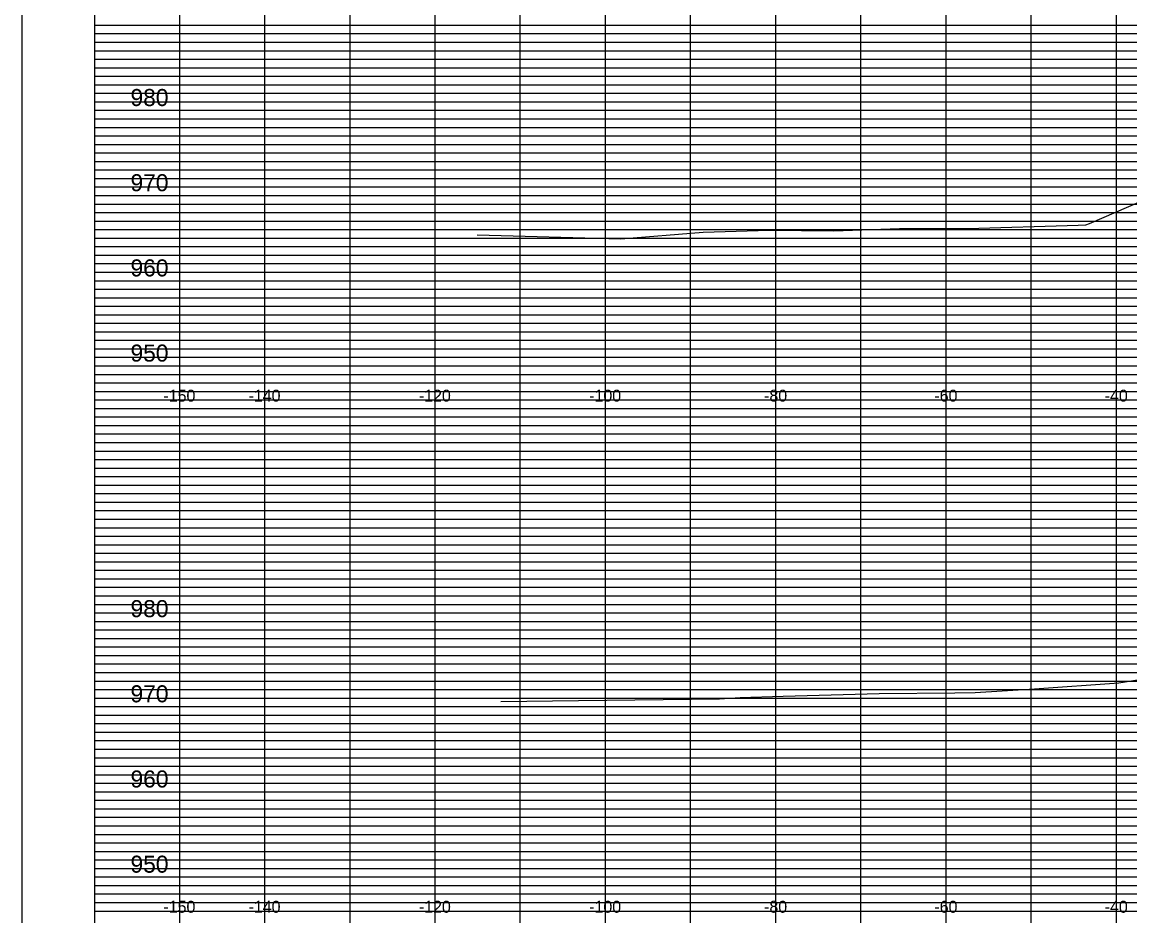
# Model space of a CAD drawing. Extents: x 2313580 to 2322968, y 282099 to 303247.
# Drawn here: x 2315290.4 to 2315420.5, y 285191.6 to 285296.5 of the extents above; entities that cross this region are included whole.
import ezdxf

# ---------------------------------------------------------------- set-up
doc = ezdxf.new("R2010")
doc.units = 0
for name, color, linetype in [('DESIGN - SCRATCH - User 1', 7, 'Continuous'), ('DESIGN - SHEET - Light Grid', 7, 'Continuous'), ('DESIGN - SHEET - Linework', 7, 'Continuous'), ('DESIGN - SHEET - Plot Shape', 7, 'Continuous'), ('DESIGN - TYPICAL - Text', 7, 'Continuous'), ('SURVEY - GROUND - Top of Ground', 7, 'Continuous')]:
    doc.layers.add(name, color=color, linetype=linetype)

msp = doc.modelspace()

# ---------------------------------------------------------------- linework, layer by layer
at = {"layer": 'DESIGN - SCRATCH - User 1'}
msp.add_line((2315298.88, 287582.67), (2315298.88, 284487.81), dxfattribs=at)
at = {"layer": 'DESIGN - SHEET - Light Grid'}
for p, q in [((2315298.88, 285295.13), (2315378.88, 285295.13)), ((2315378.88, 285295.13), (2315458.88, 285295.13)), ((2315298.88, 285294.13), (2315378.88, 285294.13)), ((2315378.88, 285294.13), (2315458.88, 285294.13)), ((2315298.88, 285293.13), (2315378.88, 285293.13)), ((2315378.88, 285293.13), (2315458.88, 285293.13)), ((2315298.88, 285292.13), (2315378.88, 285292.13)), ((2315298.88, 285291.13), (2315378.88, 285291.13)), ((2315378.88, 285292.13), (2315458.88, 285292.13)), ((2315378.88, 285291.13), (2315458.88, 285291.13)), ((2315298.88, 285290.13), (2315378.88, 285290.13)), ((2315378.88, 285290.13), (2315458.88, 285290.13)), ((2315298.88, 285289.13), (2315378.88, 285289.13)), ((2315378.88, 285289.13), (2315458.88, 285289.13)), ((2315298.88, 285288.13), (2315378.88, 285288.13)), ((2315298.88, 285287.13), (2315378.88, 285287.13)), ((2315378.88, 285288.13), (2315458.88, 285288.13)), ((2315378.88, 285287.13), (2315458.88, 285287.13)), ((2315298.88, 285285.13), (2315378.88, 285285.13)), ((2315378.88, 285285.13), (2315458.88, 285285.13)), ((2315298.88, 285284.13), (2315378.88, 285284.13)), ((2315378.88, 285284.13), (2315458.88, 285284.13)), ((2315298.88, 285283.13), (2315378.88, 285283.13)), ((2315298.88, 285282.13), (2315378.88, 285282.13)), ((2315378.88, 285283.13), (2315458.88, 285283.13)), ((2315378.88, 285282.13), (2315458.88, 285282.13)), ((2315298.88, 285281.13), (2315378.88, 285281.13)), ((2315378.88, 285281.13), (2315458.88, 285281.13)), ((2315298.88, 285280.13), (2315378.88, 285280.13)), ((2315378.88, 285280.13), (2315458.88, 285280.13)), ((2315298.88, 285279.13), (2315378.88, 285279.13)), ((2315298.88, 285278.13), (2315378.88, 285278.13)), ((2315378.88, 285279.13), (2315458.88, 285279.13)), ((2315378.88, 285278.13), (2315458.88, 285278.13)), ((2315298.88, 285277.13), (2315378.88, 285277.13)), ((2315378.88, 285277.13), (2315458.88, 285277.13)), ((2315298.88, 285275.13), (2315378.88, 285275.13)), ((2315298.88, 285274.13), (2315378.88, 285274.13)), ((2315378.88, 285275.13), (2315458.88, 285275.13)), ((2315378.88, 285274.13), (2315458.88, 285274.13)), ((2315298.88, 285273.13), (2315378.88, 285273.13)), ((2315378.88, 285273.13), (2315458.88, 285273.13)), ((2315298.88, 285272.13), (2315378.88, 285272.13)), ((2315378.88, 285272.13), (2315458.88, 285272.13)), ((2315298.88, 285271.13), (2315378.88, 285271.13)), ((2315378.88, 285271.13), (2315458.88, 285271.13)), ((2315298.88, 285270.13), (2315378.88, 285270.13)), ((2315298.88, 285269.13), (2315378.88, 285269.13)), ((2315378.88, 285270.13), (2315458.88, 285270.13)), ((2315378.88, 285269.13), (2315458.88, 285269.13)), ((2315298.88, 285268.13), (2315378.88, 285268.13)), ((2315378.88, 285268.13), (2315458.88, 285268.13)), ((2315298.88, 285267.13), (2315378.88, 285267.13)), ((2315378.88, 285267.13), (2315458.88, 285267.13)), ((2315298.88, 285265.13), (2315378.88, 285265.13)), ((2315378.88, 285265.13), (2315458.88, 285265.13)), ((2315298.88, 285264.13), (2315378.88, 285264.13)), ((2315378.88, 285264.13), (2315458.88, 285264.13)), ((2315298.88, 285263.13), (2315378.88, 285263.13)), ((2315378.88, 285263.13), (2315458.88, 285263.13)), ((2315298.88, 285262.13), (2315378.88, 285262.13)), ((2315298.88, 285261.13), (2315378.88, 285261.13)), ((2315378.88, 285262.13), (2315458.88, 285262.13)), ((2315378.88, 285261.13), (2315458.88, 285261.13)), ((2315298.88, 285260.13), (2315378.88, 285260.13)), ((2315378.88, 285260.13), (2315458.88, 285260.13)), ((2315298.88, 285259.13), (2315378.88, 285259.13)), ((2315378.88, 285259.13), (2315458.88, 285259.13)), ((2315298.88, 285258.13), (2315378.88, 285258.13)), ((2315378.88, 285258.13), (2315458.88, 285258.13)), ((2315298.88, 285257.13), (2315378.88, 285257.13)), ((2315378.88, 285257.13), (2315458.88, 285257.13)), ((2315298.88, 285255.13), (2315378.88, 285255.13)), ((2315378.88, 285255.13), (2315458.88, 285255.13)), ((2315298.88, 285254.13), (2315378.88, 285254.13)), ((2315378.88, 285254.13), (2315458.88, 285254.13)), ((2315298.88, 285253.13), (2315378.88, 285253.13)), ((2315298.88, 285252.13), (2315378.88, 285252.13)), ((2315378.88, 285253.13), (2315458.88, 285253.13)), ((2315378.88, 285252.13), (2315458.88, 285252.13)), ((2315298.88, 285251.13), (2315378.88, 285251.13)), ((2315378.88, 285251.13), (2315458.88, 285251.13)), ((2315298.88, 285250.13), (2315378.88, 285250.13)), ((2315378.88, 285250.13), (2315458.88, 285250.13)), ((2315298.88, 285249.13), (2315378.88, 285249.13)), ((2315298.88, 285248.13), (2315378.88, 285248.13)), ((2315378.88, 285249.13), (2315458.88, 285249.13)), ((2315378.88, 285248.13), (2315458.88, 285248.13)), ((2315298.88, 285247.13), (2315378.88, 285247.13)), ((2315378.88, 285247.13), (2315458.88, 285247.13)), ((2315298.88, 285245.13), (2315378.88, 285245.13)), ((2315378.88, 285245.13), (2315458.88, 285245.13)), ((2315298.88, 285244.13), (2315378.88, 285244.13)), ((2315298.88, 285243.13), (2315378.88, 285243.13)), ((2315378.88, 285244.13), (2315458.88, 285244.13)), ((2315378.88, 285243.13), (2315458.88, 285243.13)), ((2315298.88, 285242.13), (2315378.88, 285242.13)), ((2315378.88, 285242.13), (2315458.88, 285242.13)), ((2315298.88, 285241.13), (2315378.88, 285241.13)), ((2315378.88, 285241.13), (2315458.88, 285241.13)), ((2315298.88, 285240.13), (2315378.88, 285240.13)), ((2315298.88, 285239.13), (2315378.88, 285239.13)), ((2315378.88, 285240.13), (2315458.88, 285240.13)), ((2315378.88, 285239.13), (2315458.88, 285239.13)), ((2315298.88, 285238.13), (2315378.88, 285238.13)), ((2315378.88, 285238.13), (2315458.88, 285238.13)), ((2315298.88, 285237.13), (2315378.88, 285237.13)), ((2315378.88, 285237.13), (2315458.88, 285237.13)), ((2315298.88, 285235.13), (2315378.88, 285235.13)), ((2315378.88, 285235.13), (2315458.88, 285235.13)), ((2315298.88, 285234.13), (2315378.88, 285234.13)), ((2315378.88, 285234.13), (2315458.88, 285234.13)), ((2315298.88, 285233.13), (2315378.88, 285233.13)), ((2315378.88, 285233.13), (2315458.88, 285233.13)), ((2315298.88, 285232.13), (2315378.88, 285232.13)), ((2315378.88, 285232.13), (2315458.88, 285232.13)), ((2315298.88, 285231.13), (2315378.88, 285231.13)), ((2315298.88, 285230.13), (2315378.88, 285230.13)), ((2315378.88, 285231.13), (2315458.88, 285231.13)), ((2315378.88, 285230.13), (2315458.88, 285230.13)), ((2315298.88, 285229.13), (2315378.88, 285229.13)), ((2315378.88, 285229.13), (2315458.88, 285229.13)), ((2315298.88, 285228.13), (2315378.88, 285228.13)), ((2315378.88, 285228.13), (2315458.88, 285228.13)), ((2315298.88, 285227.13), (2315378.88, 285227.13)), ((2315378.88, 285227.13), (2315458.88, 285227.13)), ((2315298.88, 285225.13), (2315378.88, 285225.13)), ((2315378.88, 285225.13), (2315458.88, 285225.13)), ((2315298.88, 285224.13), (2315378.88, 285224.13)), ((2315378.88, 285224.13), (2315458.88, 285224.13)), ((2315298.88, 285223.13), (2315378.88, 285223.13)), ((2315298.88, 285222.13), (2315378.88, 285222.13)), ((2315378.88, 285223.13), (2315458.88, 285223.13)), ((2315378.88, 285222.13), (2315458.88, 285222.13)), ((2315298.88, 285221.13), (2315378.88, 285221.13)), ((2315378.88, 285221.13), (2315458.88, 285221.13)), ((2315298.88, 285220.13), (2315378.88, 285220.13)), ((2315378.88, 285220.13), (2315458.88, 285220.13)), ((2315298.88, 285219.13), (2315378.88, 285219.13)), ((2315378.88, 285219.13), (2315458.88, 285219.13)), ((2315298.88, 285218.13), (2315378.88, 285218.13)), ((2315298.88, 285217.13), (2315378.88, 285217.13)), ((2315378.88, 285218.13), (2315458.88, 285218.13)), ((2315378.88, 285217.13), (2315458.88, 285217.13)), ((2315298.88, 285215.13), (2315378.88, 285215.13)), ((2315378.88, 285215.13), (2315458.88, 285215.13)), ((2315298.88, 285214.13), (2315378.88, 285214.13)), ((2315298.88, 285213.13), (2315378.88, 285213.13)), ((2315378.88, 285214.13), (2315458.88, 285214.13)), ((2315378.88, 285213.13), (2315458.88, 285213.13)), ((2315298.88, 285212.13), (2315378.88, 285212.13)), ((2315378.88, 285212.13), (2315458.88, 285212.13)), ((2315298.88, 285211.13), (2315378.88, 285211.13)), ((2315378.88, 285211.13), (2315458.88, 285211.13)), ((2315298.88, 285210.13), (2315378.88, 285210.13)), ((2315298.88, 285209.13), (2315378.88, 285209.13)), ((2315378.88, 285210.13), (2315458.88, 285210.13)), ((2315378.88, 285209.13), (2315458.88, 285209.13)), ((2315298.88, 285208.13), (2315378.88, 285208.13)), ((2315378.88, 285208.13), (2315458.88, 285208.13)), ((2315298.88, 285207.13), (2315378.88, 285207.13)), ((2315378.88, 285207.13), (2315458.88, 285207.13)), ((2315298.88, 285205.13), (2315378.88, 285205.13)), ((2315298.88, 285204.13), (2315378.88, 285204.13)), ((2315378.88, 285205.13), (2315458.88, 285205.13)), ((2315378.88, 285204.13), (2315458.88, 285204.13)), ((2315298.88, 285203.13), (2315378.88, 285203.13)), ((2315378.88, 285203.13), (2315458.88, 285203.13)), ((2315298.88, 285202.13), (2315378.88, 285202.13)), ((2315378.88, 285202.13), (2315458.88, 285202.13)), ((2315298.88, 285201.13), (2315378.88, 285201.13)), ((2315298.88, 285200.13), (2315378.88, 285200.13)), ((2315378.88, 285201.13), (2315458.88, 285201.13)), ((2315378.88, 285200.13), (2315458.88, 285200.13)), ((2315298.88, 285199.13), (2315378.88, 285199.13)), ((2315378.88, 285199.13), (2315458.88, 285199.13)), ((2315298.88, 285198.13), (2315378.88, 285198.13)), ((2315378.88, 285198.13), (2315458.88, 285198.13)), ((2315298.88, 285197.13), (2315378.88, 285197.13)), ((2315378.88, 285197.13), (2315458.88, 285197.13)), ((2315298.88, 285195.13), (2315378.88, 285195.13)), ((2315378.88, 285195.13), (2315458.88, 285195.13)), ((2315298.88, 285194.13), (2315378.88, 285194.13)), ((2315378.88, 285194.13), (2315458.88, 285194.13)), ((2315298.88, 285193.13), (2315378.88, 285193.13)), ((2315378.88, 285193.13), (2315458.88, 285193.13)), ((2315298.88, 285192.13), (2315378.88, 285192.13)), ((2315378.88, 285192.13), (2315458.88, 285192.13))]:
    msp.add_line(p, q, dxfattribs=at)
at = {"layer": 'DESIGN - SHEET - Linework'}
for p, q in [((2315308.88, 285096.13), (2315308.88, 285306.13)), ((2315318.88, 285096.13), (2315318.88, 285306.13)), ((2315328.88, 285096.13), (2315328.88, 285306.13)), ((2315338.88, 285096.13), (2315338.88, 285306.13)), ((2315348.88, 285096.13), (2315348.88, 285306.13)), ((2315358.88, 285096.13), (2315358.88, 285306.13)), ((2315368.88, 285096.13), (2315368.88, 285306.13)), ((2315378.88, 285096.13), (2315378.88, 285306.13)), ((2315388.88, 285096.13), (2315388.88, 285306.13)), ((2315398.88, 285096.13), (2315398.88, 285306.13)), ((2315408.88, 285096.13), (2315408.88, 285306.13)), ((2315418.88, 285096.13), (2315418.88, 285306.13)), ((2315298.88, 285296.13), (2315578.88, 285296.13)), ((2315298.88, 285286.13), (2315618.88, 285286.13)), ((2315308.88, 285256.13), (2315308.88, 285286.13)), ((2315298.88, 285276.13), (2315618.88, 285276.13)), ((2315298.88, 285266.13), (2315618.88, 285266.13)), ((2315298.88, 285256.13), (2315618.88, 285256.13)), ((2315308.88, 285256.13), (2315608.88, 285256.13)), ((2315298.88, 285246.13), (2315618.88, 285246.13)), ((2315298.88, 285236.13), (2315618.88, 285236.13)), ((2315298.88, 285226.13), (2315618.88, 285226.13)), ((2315308.88, 285196.13), (2315308.88, 285226.13)), ((2315298.88, 285216.13), (2315618.88, 285216.13)), ((2315298.88, 285206.13), (2315618.88, 285206.13)), ((2315298.88, 285196.13), (2315618.88, 285196.13)), ((2315308.88, 285196.13), (2315608.88, 285196.13))]:
    msp.add_line(p, q, dxfattribs=at)
msp.add_lwpolyline([(2315298.88, 285306.13), (2315298.88, 285096.13), (2315618.88, 285096.13), (2315618.88, 285306.13), (2315298.88, 285306.13)], dxfattribs=at)
at = {"layer": 'DESIGN - SHEET - Plot Shape'}
msp.add_lwpolyline([(2315290.38, 285306.13), (2315618.88, 285306.13), (2315618.88, 285093.63), (2315290.38, 285093.63)], close=True, dxfattribs=at)
at = {"layer": 'SURVEY - GROUND - Top of Ground'}
for points in [[(2315343.8, 285271.52), (2315360.69, 285271.04), (2315370.36, 285271.81), (2315378.09, 285272.06), (2315385.68, 285271.99), (2315393.39, 285272.26), (2315401.42, 285272.25), (2315414.4, 285272.64), (2315415.3, 285272.69), (2315415.71, 285272.85), (2315424.67, 285276.7)], [(2315346.58, 285216.71), (2315355.72, 285216.83), (2315372.28, 285217.04), (2315374.68, 285217.19), (2315379.75, 285217.36), (2315391.02, 285217.67), (2315399.91, 285217.76), (2315402.3, 285217.78), (2315409.25, 285218.21), (2315419.17, 285218.91), (2315430.44, 285220.72)]]:
    msp.add_lwpolyline(points, dxfattribs=at)

# ---------------------------------------------------------------- texts
at = {"layer": 'DESIGN - SHEET - Linework'}
for p in [(2315308.88, 285256.13), (2315308.88, 285196.13)]:
    msp.add_text('-', height=0.0001, dxfattribs=at).set_placement(p)
at = {"layer": 'DESIGN - TYPICAL - Text'}
for s, height, p in [('980', 2, (2315303.1, 285286.63)), ('970', 2, (2315303.1, 285276.63)), ('960', 2, (2315303.1, 285266.63)), ('950', 2, (2315303.1, 285256.63)), ('-150', 1.4, (2315306.97, 285251.93)), ('-140', 1.4, (2315316.97, 285251.93)), ('-120', 1.4, (2315336.97, 285251.93)), ('-100', 1.4, (2315356.97, 285251.93)), ('-80', 1.4, (2315377.51, 285251.93)), ('-60', 1.4, (2315397.51, 285251.93)), ('-40', 1.4, (2315417.51, 285251.93)), ('980', 2, (2315303.1, 285226.63)), ('970', 2, (2315303.1, 285216.63)), ('960', 2, (2315303.1, 285206.63)), ('950', 2, (2315303.1, 285196.63)), ('-150', 1.4, (2315306.97, 285191.93)), ('-140', 1.4, (2315316.97, 285191.93)), ('-120', 1.4, (2315336.97, 285191.93)), ('-100', 1.4, (2315356.97, 285191.93)), ('-80', 1.4, (2315377.51, 285191.93)), ('-60', 1.4, (2315397.51, 285191.93)), ('-40', 1.4, (2315417.51, 285191.93))]:
    msp.add_text(s, height=height, dxfattribs=at).set_placement(p)

doc.saveas('drawing.dxf')
